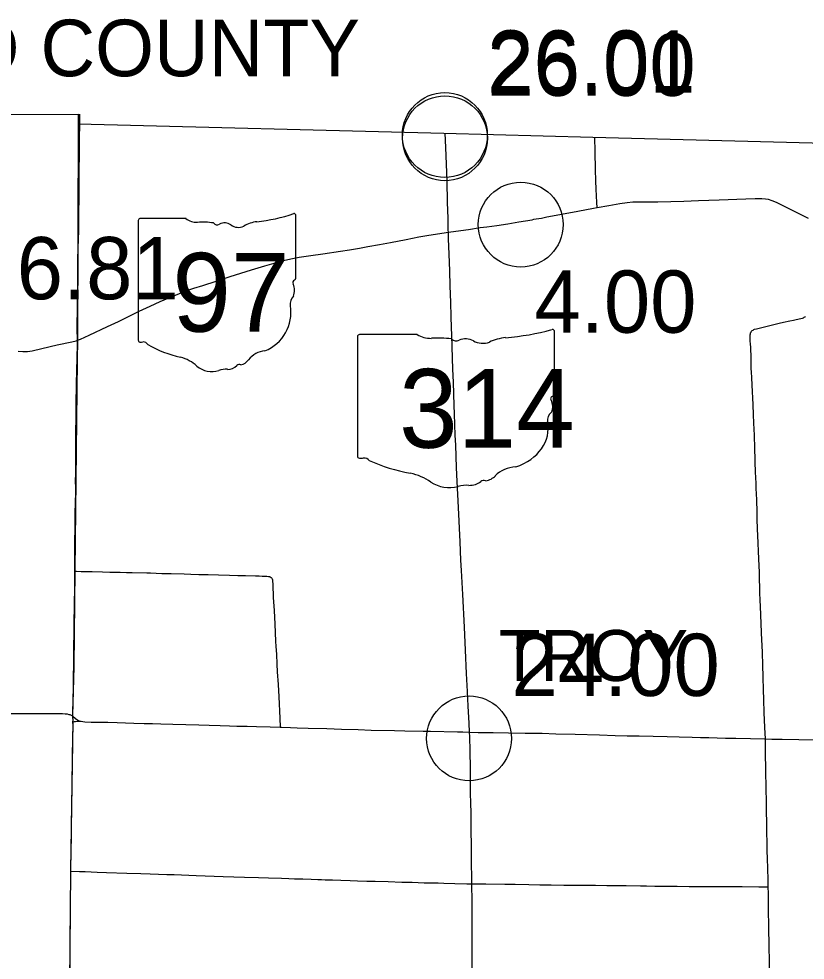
# Model space of a CAD drawing. Extents: x 1813937 to 1948437, y 826606 to 1022856.
# Drawn here: x 1914981 to 1928879, y 972609 to 989247 of the extents above; entities that cross this region are included whole.
import ezdxf

# ---------------------------------------------------------------- set-up
doc = ezdxf.new("R2010")
doc.units = 0
for name, color, linetype in [('Default', 7, 'Continuous'), ('GM_X_Adjacent_County_Text', 7, 'Continuous'), ('GM_X_County', 7, 'Continuous'), ('GM_X_County_Road', 7, 'Continuous'), ('GM_X_State_Route', 7, 'Continuous'), ('GM_X_State_Shield', 7, 'Continuous'), ('GM_X_Township', 7, 'Continuous'), ('GM_X_Township_Road', 7, 'Continuous'), ('GM_X_Township_Text', 7, 'Continuous')]:
    doc.layers.add(name, color=color, linetype=linetype)

msp = doc.modelspace()

# ---------------------------------------------------------------- linework, layer by layer
at = {"layer": 'Default'}
for centre in [(1922510, 987192), (1922513, 987136), (1923852, 985610), (1922939, 976529)]:
    msp.add_circle(centre, 750, dxfattribs=at)
at = {"layer": 'GM_X_County'}
msp.add_lwpolyline([(1892176, 987990), (1895013, 987926), (1897647, 987858), (1900287, 987794), (1904231, 987686), (1905517, 987636), (1906801, 987606), (1908915, 987558), (1916031, 987559), (1916031, 987390), (1922491, 987223), (1925127, 987155), (1933106, 986948)], dxfattribs=at)
at = {"layer": 'GM_X_County_Road'}
for points in [[(1916057, 987391), (1916059, 987456), (1916058, 987561)], [(1916016, 983565), (1916015, 983766), (1916018, 984176), (1916019, 984389), (1916021, 984487), (1916021, 984635), (1916022, 984733), (1916023, 984848), (1916024, 984995), (1916029, 985191), (1916040, 985504), (1916044, 985833), (1916048, 986060), (1916047, 986374), (1916047, 986521), (1916052, 986898), (1916054, 987029), (1916055, 987160), (1916057, 987357), (1916057, 987391)], [(1915971, 979485), (1915971, 979488), (1915972, 980045), (1915975, 980209), (1915978, 980422), (1915978, 980554), (1915981, 980652), (1915983, 980734), (1915986, 980832), (1915986, 980897), (1915986, 980963), (1915985, 981078), (1915986, 981209), (1915988, 981340), (1915988, 981684), (1915990, 981865), (1915994, 982274), (1915997, 982455), (1916002, 982766), (1916007, 983061), (1916011, 983225), (1916016, 983520), (1916016, 983565)], [(1915937, 976924), (1915937, 976948), (1915944, 977243), (1915946, 977391), (1915950, 977637), (1915952, 977817), (1915953, 977899), (1915953, 977997), (1915955, 978145), (1915959, 978390), (1915961, 978472), (1915961, 978571), (1915962, 978685), (1915963, 978767), (1915965, 978915), (1915968, 979177), (1915970, 979357), (1915971, 979485)], [(1914754, 976969), (1914984, 976968), (1915098, 976968), (1915246, 976968), (1915311, 976969), (1915409, 976970), (1915655, 976970), (1915754, 976969), (1915803, 976965), (1915835, 976961), (1915867, 976954), (1915882, 976949), (1915897, 976943), (1915937, 976924)], [(1915901, 974182), (1915901, 974220), (1915906, 974554), (1915910, 974783), (1915913, 974980), (1915919, 975357), (1915924, 975702), (1915931, 976194), (1915938, 976554), (1915939, 976751), (1915938, 976819)], [(1915937, 976924), (1915982, 976881), (1915991, 976873), (1916018, 976855), (1916033, 976847), (1916049, 976841), (1916065, 976836), (1916069, 976835)], [(1915938, 976819), (1915939, 976850), (1915937, 976924)], [(1915938, 976819), (1915960, 976825), (1915983, 976830), (1916015, 976832), (1916037, 976834), (1916069, 976835)], [(1916069, 976835), (1916081, 976832), (1916114, 976826), (1916146, 976823), (1916261, 976818), (1916557, 976813), (1916720, 976807), (1917016, 976796), (1917199, 976793), (1917342, 976790), (1917491, 976789), (1917704, 976781), (1918163, 976767), (1918343, 976764), (1918540, 976757), (1918704, 976752), (1918834, 976748), (1919014, 976746), (1919180, 976740), (1919423, 976731), (1919598, 976728)], [(1919598, 976728), (1919624, 976728), (1919785, 976722), (1919899, 976717), (1920096, 976710), (1920424, 976701), (1920686, 976694), (1920981, 976685), (1921211, 976677), (1921621, 976666), (1921801, 976663), (1922129, 976658), (1922259, 976656), (1922734, 976645), (1922831, 976643), (1922947, 976639)], [(1922947, 976639), (1923098, 976636), (1923226, 976635), (1923364, 976634), (1923635, 976629), (1923930, 976624), (1924228, 976619), (1924471, 976611), (1924816, 976602), (1925242, 976589), (1925521, 976583), (1925734, 976577), (1925865, 976575), (1925947, 976573), (1926193, 976566), (1926439, 976561), (1926652, 976554), (1926881, 976549), (1927029, 976546), (1927176, 976543), (1927324, 976540), (1927471, 976535), (1927652, 976531), (1927914, 976526), (1928160, 976521), (1928175, 976521)], [(1928175, 976521), (1928291, 976518), (1928471, 976515), (1928766, 976511), (1929209, 976506)], [(1915901, 974182), (1916055, 974178), (1916153, 974174), (1916366, 974167), (1916530, 974161), (1916890, 974149), (1917136, 974143), (1917300, 974137), (1917447, 974131), (1917594, 974125), (1917725, 974121), (1918118, 974105), (1918593, 974091), (1918970, 974079), (1919216, 974070), (1919396, 974063), (1919621, 974056)], [(1919621, 974056), (1919625, 974056), (1919756, 974051), (1919854, 974049), (1920002, 974044), (1920149, 974038), (1920264, 974035), (1920329, 974034), (1920395, 974032), (1920526, 974027), (1920673, 974024), (1920837, 974020), (1920968, 974014), (1921132, 974008), (1921213, 974006), (1921279, 974005), (1921508, 973997), (1921753, 973990), (1921934, 973985), (1922147, 973979), (1922278, 973976), (1922392, 973974), (1922491, 973970), (1922687, 973964), (1922899, 973959), (1922987, 973958)]]:
    msp.add_lwpolyline(points, dxfattribs=at)
at = {"layer": 'GM_X_State_Route'}
for points in [[(1922999, 972223), (1922995, 972666), (1922994, 972814), (1922994, 972978), (1922994, 973125), (1922993, 973257), (1922992, 973388), (1922991, 973519), (1922991, 973634), (1922991, 973732), (1922989, 973864), (1922988, 973946), (1922987, 973958), (1922985, 974110), (1922984, 974274), (1922982, 974389), (1922979, 974651), (1922976, 974881), (1922973, 975226), (1922970, 975373), (1922966, 975570), (1922964, 975734), (1922965, 975882), (1922963, 975997), (1922958, 976309), (1922951, 976555), (1922947, 976639), (1922940, 976801), (1922925, 977096), (1922912, 977357), (1922895, 977677), (1922876, 978087), (1922855, 978496), (1922827, 979070), (1922804, 979496), (1922794, 979677), (1922782, 980004), (1922753, 980611), (1922730, 981070), (1922718, 981316), (1922702, 981709), (1922695, 981889), (1922679, 982266), (1922674, 982414), (1922661, 982824), (1922654, 983053), (1922641, 983447), (1922633, 983658), (1922628, 983793), (1922623, 983988), (1922617, 984231), (1922604, 984530), (1922596, 984790), (1922584, 985086), (1922577, 985361), (1922573, 985475), (1922572, 985511), (1922567, 985725), (1922559, 986003), (1922549, 986381), (1922527, 986971), (1922516, 987224)], [(1914970, 983370), (1915052, 983365), (1915133, 983368), (1915214, 983378), (1915390, 983418), (1915661, 983483), (1915918, 983537), (1915997, 983558), (1916016, 983565), (1916073, 983585), (1916222, 983654), (1916549, 983807), (1916741, 983899), (1917110, 984078), (1917303, 984169), (1917482, 984252), (1917648, 984323), (1917923, 984431), (1918077, 984486), (1918234, 984536), (1918468, 984610), (1918717, 984694), (1919094, 984809), (1919329, 984879), (1919534, 984939), (1919660, 984975), (1919788, 985007), (1919933, 985035), (1920144, 985064), (1920355, 985093), (1920664, 985138), (1920826, 985162), (1921004, 985192), (1921148, 985221), (1921358, 985261), (1921551, 985296), (1921825, 985349), (1922050, 985391), (1922228, 985421), (1922573, 985475), (1922617, 985481), (1922926, 985526), (1923137, 985556), (1923251, 985569), (1923429, 985593), (1923623, 985624), (1923817, 985659), (1924054, 985697), (1924082, 985703), (1924125, 985709), (1924219, 985726), (1924267, 985735), (1924315, 985745), (1924411, 985763), (1924571, 985794), (1924862, 985847), (1925136, 985899), (1925204, 985912), (1925410, 985950), (1925604, 985984), (1925734, 986002), (1925832, 986011), (1925931, 986014), (1926275, 986012), (1926505, 986018), (1926734, 986026), (1926996, 986035), (1927357, 986048), (1927832, 986067), (1927996, 986073), (1928111, 986072), (1928177, 986066), (1928226, 986057), (1928289, 986038), (1928365, 986006), (1928557, 985912), (1928931, 985721)]]:
    msp.add_lwpolyline(points, dxfattribs=at)
at = {"layer": 'GM_X_State_Shield'}
for p, q in [((1919877, 984664), (1919877, 985770)), ((1917093, 985681), (1917093, 983568)), ((1917936, 985717), (1917120, 985717)), ((1919877, 984665), (1919877, 984664)), ((1920968, 983631), (1920968, 981517)), ((1922021, 983667), (1921002, 983667)), ((1924448, 982614), (1924448, 983719)), ((1924448, 982614), (1924448, 982614))]:
    msp.add_line(p, q, dxfattribs=at)
for centre, radius, start, end in [((1918885, 988599), 2953, 275.8445, 288.9065), ((1919846, 985774), 31, 351.8621, 97.738), ((1917125, 985686), 32.3, 98.1301, 188.1301), ((1918130, 985963), 313, 231.6195, 271.1119), ((1918234, 984531), 1123, 80.4867, 94.9883), ((1918489, 985697), 90.3, 219.7921, 297.1024), ((1918621, 985452), 188, 54.4667, 119.1411), ((1918863, 985787), 226, 233.8562, 294.8282), ((1919262, 985072), 594, 97.3462, 120.7689), ((1919870, 984583), 48, 107.944, 210.337), ((1919844, 984660), 33.2, 289.6038, 7.7341), ((1919565, 984443), 288, 340.033, 23.6496), ((1919988, 984202), 210, 136.8065, 186.9296), ((1919051, 984061), 739, 292.3089, 8.9858), ((1917125, 983563), 32.5, 171.9584, 258.3066), ((1917130, 983779), 248, 267.339, 280.6039), ((1917181, 983446), 89.5, 29.7484, 93.2717), ((1918311, 985345), 2132, 240.4129, 257.1985), ((1919362, 982974), 404, 94.4031, 142.5768), ((1917676, 982618), 667, 47.1842, 75.836), ((1918397, 983435), 423, 230.7004, 286.2918), ((1918673, 983277), 226, 268.777, 315.5493), ((1918877, 983072), 63.5, 65.7517, 132.6484), ((1918850, 983363), 239, 282.8732, 323.2771), ((1918642, 982705), 348, 85.6951, 111.2099)]:
    msp.add_arc(centre, radius, start, end, dxfattribs=at)
for centre, major_axis, start_param, end_param in [((1921008, 983635), (40.3, 0), 1.712693, 3.28349), ((1922264, 983912), (391, 0), 4.042523, 4.731795), ((1922394, 982481), (1404, 0), 1.404758, 1.657858), ((1923679, 983022), (743, 0), 1.699011, 2.107814), ((1923208, 986548), (3691, 0), 4.814394, 5.042369), ((1924410, 983724), (38.7, 0), 6.141152, 7.989035), ((1922713, 983646), (113, 0), 3.836095, 5.185415), ((1922878, 983402), (235, 0), 0.950623, 2.079405), ((1923181, 983737), (282, 0), 4.081561, 5.145723), ((1924407, 982610), (41.5, 0), 5.05454, 6.418171), ((1924439, 982533), (60, 0), 1.883978, 3.671073), ((1924058, 982393), (360, 0), 5.934695, 6.695948), ((1924587, 982151), (262, 0), 2.387724, 3.262537), ((1923415, 982011), (923, 0), 5.101752, 6.440018), ((1921008, 981513), (40.7, 0), 3.00124, 4.508301), ((1921014, 981729), (310, 0), 4.665946, 4.897461), ((1921078, 981395), (112, 0), 0.519207, 1.627899), ((1922491, 983294), (2665, 0), 4.195997, 4.488961), ((1923804, 980924), (506, 0), 1.647645, 2.488434), ((1921696, 980568), (834, 0), 0.823519, 1.323587), ((1923164, 981313), (298, 0), 4.937069, 5.64225), ((1922598, 981385), (529, 0), 4.026481, 4.996735), ((1922904, 980654), (435, 0), 1.495662, 1.94098), ((1922943, 981227), (282, 0), 4.691044, 5.507374), ((1923198, 981022), (79.4, 0), 1.147584, 2.315152)]:
    msp.add_ellipse(centre, major_axis=major_axis, ratio=0.8, start_param=start_param, end_param=end_param, dxfattribs=at)
at = {"layer": 'GM_X_Township'}
msp.add_lwpolyline([(1916031, 987559), (1916031, 987390), (1916016, 983574), (1916012, 983206), (1915968, 979502), (1915954, 977797), (1915930, 976934), (1915938, 976821), (1915894, 974189), (1915874, 972112), (1915857, 970374), (1915816, 966860), (1915806, 966233), (1915788, 965343), (1915744, 960965)], dxfattribs=at)
at = {"layer": 'GM_X_Township_Road'}
for points in [[(1925204, 985912), (1925197, 985999), (1925185, 986237), (1925182, 986386), (1925176, 986584), (1925167, 986896), (1925160, 987157)], [(1927924, 983187), (1927923, 983238), (1927922, 983306), (1927919, 983384), (1927916, 983436), (1927913, 983500), (1927909, 983550), (1927907, 983599), (1927908, 983630), (1927908, 983647), (1927909, 983664), (1927911, 983679), (1927915, 983697), (1927923, 983711), (1927932, 983724), (1927944, 983736), (1927957, 983746), (1927971, 983754), (1927986, 983761), (1928017, 983770), (1928161, 983805), (1928257, 983828), (1928417, 983865), (1928497, 983883), (1928609, 983909), (1928673, 983922), (1928721, 983933), (1928801, 983950), (1928833, 983958), (1928848, 983964), (1928863, 983972), (1928876, 983982), (1928887, 983994)], [(1928085, 978965), (1928080, 979106), (1928078, 979196), (1928074, 979344), (1928071, 979459), (1928061, 979704), (1928043, 980114), (1928038, 980229), (1928033, 980409), (1928031, 980457), (1928030, 980505), (1928028, 980538), (1928022, 980735), (1928016, 980866), (1928014, 980932), (1928011, 981030), (1928006, 981145), (1928003, 981227), (1927997, 981424), (1927990, 981686), (1927984, 981850), (1927981, 981899), (1927978, 981981), (1927968, 982243), (1927959, 982439), (1927954, 982538), (1927949, 982668), (1927944, 982766), (1927935, 982912), (1927931, 982994), (1927927, 983074), (1927925, 983174), (1927924, 983187)], [(1915971, 979485), (1916000, 979484), (1916082, 979481), (1916163, 979480), (1916278, 979478), (1916458, 979473), (1916590, 979469), (1916770, 979464), (1916885, 979461), (1916983, 979459), (1917246, 979454), (1917311, 979453), (1917508, 979446), (1917672, 979441), (1917901, 979435), (1918019, 979433), (1918164, 979428), (1918328, 979423), (1918509, 979417), (1918706, 979412), (1918854, 979408), (1918985, 979406), (1919166, 979402), (1919231, 979401), (1919280, 979399), (1919363, 979397), (1919395, 979393), (1919411, 979389), (1919426, 979383), (1919440, 979374), (1919451, 979362), (1919459, 979348), (1919464, 979332), (1919467, 979316), (1919470, 979250), (1919479, 979020), (1919492, 978791), (1919505, 978545), (1919520, 978249), (1919525, 978151), (1919533, 978020), (1919542, 977839), (1919548, 977708), (1919563, 977479), (1919574, 977265), (1919592, 976888), (1919598, 976728)], [(1928175, 976521), (1928167, 976721), (1928157, 976984), (1928149, 977213), (1928144, 977393), (1928138, 977607), (1928130, 977836), (1928123, 978033), (1928116, 978180), (1928113, 978262), (1928107, 978409), (1928095, 978704), (1928088, 978868), (1928085, 978965)], [(1928226, 973903), (1928223, 974049), (1928221, 974213), (1928214, 974426), (1928210, 974524), (1928207, 974655), (1928204, 974901), (1928196, 975377), (1928190, 975672), (1928185, 975934), (1928182, 976049), (1928180, 976197), (1928178, 976312), (1928176, 976492), (1928175, 976521)], [(1915876, 971659), (1915877, 971687), (1915878, 971868), (1915882, 972048), (1915882, 972147), (1915882, 972311), (1915884, 972442), (1915886, 972622), (1915890, 972950), (1915893, 973492), (1915895, 973754), (1915898, 973934), (1915899, 974033), (1915900, 974115), (1915901, 974182)], [(1922987, 973958), (1923237, 973956), (1923568, 973953), (1923752, 973952), (1923994, 973947), (1924187, 973942), (1924387, 973939), (1924616, 973935), (1924895, 973933), (1925092, 973933), (1925174, 973933), (1925372, 973930), (1925714, 973927), (1925967, 973924), (1926075, 973922), (1926223, 973920), (1926436, 973918), (1926615, 973916), (1926830, 973914), (1927126, 973913), (1927323, 973911), (1927765, 973909), (1928062, 973905), (1928189, 973904), (1928226, 973903)], [(1928272, 971231), (1928267, 971504), (1928267, 971592), (1928263, 971739), (1928261, 971820), (1928258, 971918), (1928256, 972131), (1928254, 972246), (1928251, 972393), (1928247, 972656), (1928244, 972787), (1928240, 972967), (1928239, 973082), (1928236, 973229), (1928232, 973475), (1928228, 973787), (1928226, 973903)]]:
    msp.add_lwpolyline(points, dxfattribs=at)

# ---------------------------------------------------------------- texts
at = {"layer": 'Default'}
for s, p in [('26.01', (1923260, 987942)), ('26.00', (1923263, 987886)), ('6.81', (1914944, 984290)), ('4.00', (1924095, 983699)), ('24.00', (1923689, 977279))]:
    msp.add_text(s, height=1100, dxfattribs=at).set_placement(p)
at = {"layer": 'GM_X_Adjacent_County_Text'}
msp.add_text('RICHLAND COUNTY', height=1000, dxfattribs=at).set_placement((1908157, 988232))
at = {"layer": 'GM_X_State_Shield'}
for s, p in [('97', (1917694, 983717)), ('314', (1921702, 981666))]:
    msp.add_text(s, height=1392.2, dxfattribs=at).set_placement(p)
at = {"layer": 'GM_X_Township_Text'}
msp.add_text('TROY', height=900, rotation=0, dxfattribs=at).set_placement((1923467, 977544))

doc.saveas('drawing.dxf')
